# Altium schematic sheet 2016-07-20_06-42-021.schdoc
size 236 x 111 mm; SheetNumber: 1; SheetTotal: 1
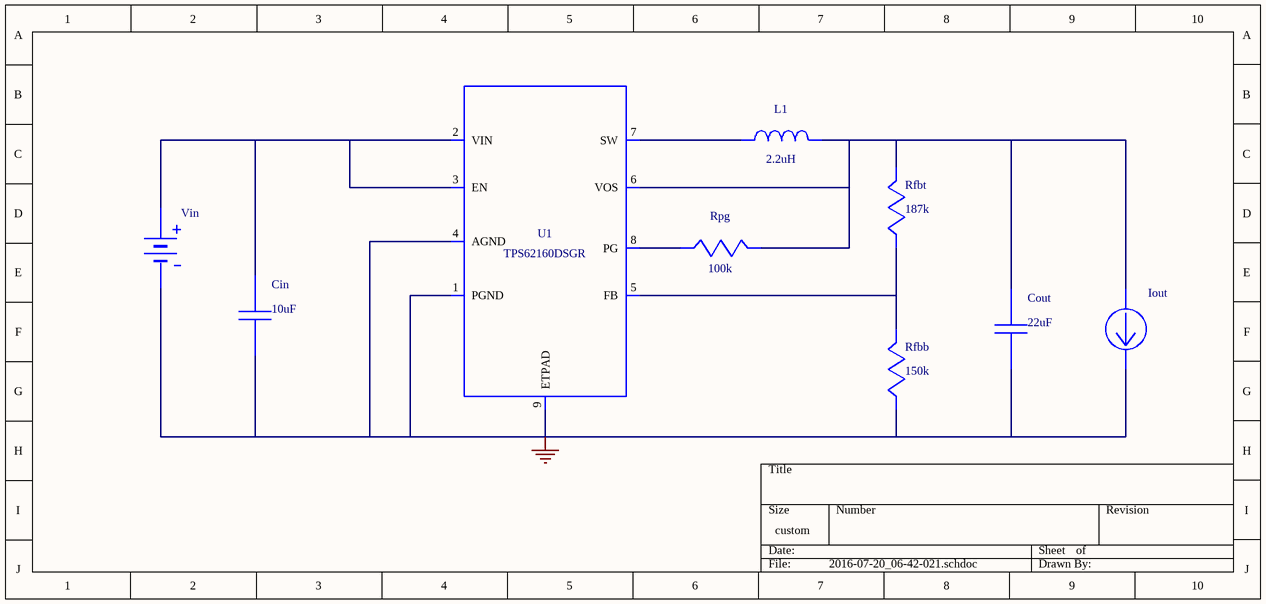
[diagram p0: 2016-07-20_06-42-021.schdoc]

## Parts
Cin  value 10uF  (hidden comment: LMK212BJ106KG-T)
Cout  value 22uF  (hidden comment: GRM32ER71C226KE18L)
Iout  WB_CURRENT_LOAD  (value not drawn)
L1  value 2.2uH  (hidden comment: XFL4020-222MEB)
Rfbb  value 150k  (hidden comment: CRCW0402150KFKED)
Rfbt  value 187k  (hidden comment: CRCW0402187KFKED)
Rpg  value 100k  (hidden comment: CRCW0402100KFKED)
U1  TPS62160DSGR
Vin  WB_BATTERY  (value not drawn)

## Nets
0: Cin.2 Cout.2 Iout.2(-) Rfbb.2 U1.1(PGND) U1.4(AGND) U1.9(ETPAD) Vin.2(-)
NetCin_1: Cin.1 U1.2(VIN) U1.3(EN) Vin.1(+)
NetCout_1: Cout.1 Iout.1(+) L1.2 Rfbt.1 Rpg.1 U1.6(VOS)
NetL1_1: L1.1 U1.7(SW)
NetRfbb_1: Rfbb.1 Rfbt.2 U1.5(FB)
NetRpg_2: Rpg.2 U1.8(PG)

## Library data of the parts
Cin = LMK212BJ106KG-T: Manufacturer Name: Taiyo Yuden
Cout = GRM32ER71C226KE18L: GRM32ER71C226KE1; Manufacturer Name: MuRata
L1 = XFL4020-222MEB: Manufacturer Name: Coilcraft
Rfbb = CRCW0402150KFKED: Manufacturer Name: Vishay-Dale
Rfbt = CRCW0402187KFKED: Manufacturer Name: Vishay-Dale
Rpg = CRCW0402100KFKED: Manufacturer Name: Vishay-Dale
U1 = TPS62160DSGR: Manufacturer Name: Texas Instruments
